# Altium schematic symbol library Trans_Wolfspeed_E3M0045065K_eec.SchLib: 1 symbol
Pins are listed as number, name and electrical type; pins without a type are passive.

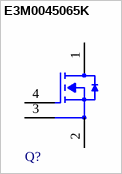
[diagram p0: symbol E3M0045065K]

## E3M0045065K
designator Q?  (value not drawn)
pins: 1 Drain, 2 Power Source, 3 Driver Source, 4 Gate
